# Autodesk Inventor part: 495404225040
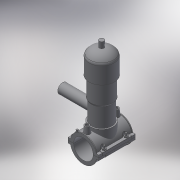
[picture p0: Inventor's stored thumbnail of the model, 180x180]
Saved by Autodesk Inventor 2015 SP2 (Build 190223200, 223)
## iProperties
Created: 2017-07
Part Number: 495404225040
Material: Generic
Description: PLASSON TAPPING VALVE 225-40
Document SubType Name: Modeling
Designer: KIM
Density: 1 g/cm^3
Appearance: Default
Author: KIM
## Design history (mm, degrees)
derived "495404-4954S4.ipt"
feature "Solid1::495404-4954S4.ipt"
feature "Solid2::495404-4954S4.ipt"
tag "TaggingFeature1"
body "Solid1"
body "Solid2"
other parameters: "d0" = 225, "d2" = 295.1, "d3" = 56.25, "d4" = 176, "d5" = 0, "d6" = 0.1, "d8" = 0, "d19" = 6, "d20" = 6, "d21" = 105.6, "d23" = 0, "d24" = 52.8, "d26" = 0, "d27" = 3, "d28" = 3, "d29" = 3, "d30" = 75, "d31" = 6, "d32" = 0, "d33" = 0, "d34" = 0.6, "d40" = 136.89, "d47" = 177.625, "d70" = 15, "d72" = 0, "d73" = 6, "d75" = 5, "d76" = 0, "d77" = 11.25, "d78" = 142.5, "d79" = 15, "d80" = 70.4, "d82" = 5 deg, "d84" = 4, "d85" = 14, "d86" = 0, "d87" = 3, "d88" = 0, "d89" = 1, "d90" = 1, "d91" = 140.8, "d92" = 0, "d93" = 0.5, "d94" = 118.42105, "d96" = 271.1475, "d97" = 3.52, "d98" = 0, "d120" = 140 deg, "d121" = 24.228, "d122" = 20 deg, "d123" = 526.5, "d124" = 157.95, "d126" = 0, "d143" = 231.75, "d145" = 29.42308, "d149" = 3.375, "d150" = 32.36538, "d153" = 176, "d154" = 0, "d156" = 131.625, "d157" = 160 deg, "d159" = 7.65, "d161" = 3.375, "d162" = 105.6, "d163" = 0, "d164" = 112.5, "d167" = 22.5, "d168" = 128.41463, "d170" = 3.375, "d172" = 0, "d173" = 1, "d175" = 112.5, "d176" = 20 deg, "d177" = 15.75, "d178" = 38.25, "d180" = 0, "d183" = 15.3, "d184" = 12.6, "d185" = 57.2, "d186" = 57.2, "d187" = 131.625, "d188" = 11.475, "d189" = 15.75, "d190" = 0, "d191" = 197.4375, "d193" = 7.65, "d194" = 4.4, "d195" = 90 deg, "d197" = 0, "d199" = 0, "d205" = 14.64, "d206" = 81.33333, "d207" = 244, "d208" = 224.48, "d209" = 207.4, "d210" = 200.08, "d211" = 146.4, "d212" = 85.4, "d213" = 65.88, "d214" = 73.2, "d216" = 21.96, "d217" = 70.76, "d218" = 80.52, "d220" = 225, "d222" = 0, "d223" = 263.25, "d224" = 137, "d225" = 46, "d229" = 137, "d230" = 0, "d_" = 225, "B_" = 227, "H_" = 137, "L_" = 176, "d_t" = 6, "H_1" = 46, "H_2" = 244, "d148" = 3.375, "d160" = 3.375, "d169" = 3.375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
